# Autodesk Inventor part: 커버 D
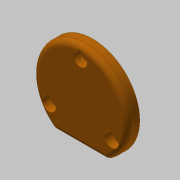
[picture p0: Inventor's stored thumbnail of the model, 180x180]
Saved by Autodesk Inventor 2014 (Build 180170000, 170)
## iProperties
Created: 2020-04
Part Number: 커버 D
Material: 알루미늄 6061
Document SubType Name: Modeling
Designer: mduedu
Density: 2.71 g/cm^3
Mass: 32.8423 g
Surface Area: 61.5912 cm^2
Volume: 12.1189 cm^3
Appearance: Orange
Author: mduedu
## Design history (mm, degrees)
sketch "스케치1"
  geometry: C1 r 26 at (0, 0); 1 further point
  constraints: 1 centre point, 1 coincident
  dimensions: "d0" = 52 diameter of C1
extrude "돌출1" new body sketch "스케치1" distance "d1" = 7; taper "d2" = 0 deg
sketch "스케치2"
  geometry: L1 (-14.62, -21.5)-(14.62, -21.5); A1 r 26 centre (0, 0) between (-14.62, -21.5) and (14.62, -21.5) reference; 1 further point
  constraints: 2 end point, 2 point on circle, 1 horizontal
  dimensions: "d3" = 21.5 distance from line of L1 point (0, 0)
extrude "돌출2" cut sketch "스케치2" stored distance "d4" = 7; taper "d5" = 0 deg
fillet "모깎기1" dims "d6" = 3
fillet "모깎기2" dims "d7" = 3
sketch "스케치3" dims "d8" = 40
  geometry: 3 further points
  constraints: 2 vertical alignment, 1 coincident, 2 other
hole "구멍1" sketch "스케치3" at (0, 20) diameter "d9" = 4.5; stored, may be unused: countersink angle "d13" = 90 deg, drill point angle "d15" = 118 deg; dims "d10" = 6, "d11" = 8, "d12" = 4.4, "d14" = 8
sketch "스케치4"
  geometry: C1 r 14 at (0, 0); 1 further point
  constraints: 1 centre point, 1 coincident
  dimensions: "d19" = 28 diameter of C1
extrude "돌출3" join sketch "스케치4" distance "d20" = 4; taper "d21" = 0 deg
sketch "스케치5"
  geometry: C1 r 12 at (0, 0); 1 further point
  constraints: 1 centre point, 1 coincident
  dimensions: "d22" = 24 diameter of C1
extrude "돌출4" cut sketch "스케치5" distance "d23" = 8; taper "d24" = 0 deg
fillet "모깎기3" dims "d25" = 3
chamfer "모따기1" distance "d26" = 0.5; stored, may be unused: second distance "d27" = 2, angle "d28" = 45 deg
node "솔리드1"
pattern_circular "원형 패턴1" dims angle "d17" = 360 deg
node "투영된 루프1"
